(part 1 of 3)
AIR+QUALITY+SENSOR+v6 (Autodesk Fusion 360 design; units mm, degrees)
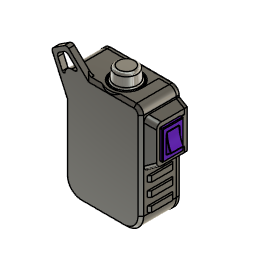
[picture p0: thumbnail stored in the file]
part number: flat_cable
part number: smd_capacitor (7)
part number: SOT-23_XC6206 v3
part number: 472_smd_resistor (1)
part number: smd_capacitor (6)
part number: smd_capacitor (5)
part number: smd_capacitor (4)
part number: smd_capacitor (3)
part number: board
part number: screen
part number: pin_header
part number: soldering
part number: smd_capacitor
part number: smd_capacitor (1)
part number: 914_smd_resistor
part number: 472_smd_resistor
part number: t4_smd_diode
part number: smd_capacitor (2)
sketch "Sketch1" plane through (0, 0, 0) normal (0, 0, 1) x axis (1, 0, 0)
  line L1 (13.5, 15.5) -> (-18.5, 15.5)
  line L2 (13.5, -4.5) -> (13.5, 15.5)
  line L3 (-18.5, -4.5) -> (13.5, -4.5)
  line L4 (-18.5, 15.5) -> (-18.5, -4.5)
  line L5 (13.5, 5.5) -> (-18.5, 5.5)
  line L6 (-2.5, -4.5) -> (-2.5, 15.5)
  line L7 (11, 13) -> (-16, 13)
  line L8 (11, -2) -> (11, 13)
  line L9 (-16, -2) -> (11, -2)
  line L10 (-16, 13) -> (-16, -2)
  line L11 (11.5, -9) -> (11.5, 19)
  circle C1 centre (-16, 13) radius 1.5
  circle C2 centre (-16, -2) radius 1.5
  circle C3 centre (11, 13) radius 1.5
  circle C4 centre (11, -2) radius 1.5
  circle C5 centre (1.5, 5.5) radius 10
  point P6 (-18.5, 5.5)
  point P7 (13.5, 5.5)
  point P8 (-2.5, 15.5)
  point P9 (-2.5, -4.5)
  point P10 (-16, 13)
  point P14 (-16, 13)
  point P13 (-16, -2)
  point P15 (-16, -2)
  point P11 (11, 13)
  point P16 (11, 13)
  point P12 (11, -2)
  point P17 (11, -2)
  point P2 (-18.5, 15.5)
  point P5 (-18.5, -4.5)
  point P3 (13.5, 15.5)
  horizontal L1
  vertical L2
  horizontal L3
  vertical L4
  midpoint L4 P6
  midpoint L2 P7
  midpoint L1 P8
  midpoint L3 P9
  horizontal L7
  vertical L8
  horizontal L9
  vertical L10
  symmetric L5 L7 L9
  symmetric L6 L8 L10
  coincident P10 P14
  coincident P13 P15
  coincident P11 P16
  coincident P12 P17
  perpendicular L3 L11
  dimension "d1" distance P2 P5 = 20
  dimension "d2" distance P2 P3 = 32
  dimension "d3" distance P10 P11 = 27
  dimension "d4" distance P10 P13 = 15
  dimension "d5" diameter C1 = 3
  dimension "d6" diameter C2 = 3
  dimension "d7" diameter C3 = 3
  dimension "d8" diameter C4 = 3
  dimension "d9" distance L2 L11 = 2
  dimension "d10" diameter C5 = 20
extrude "Extrude1" new body sketch "Sketch1" profile of L1 L2 L3 L4 C1 C2 C3 C4 C5 against normal blind 1.1
extrude "Extrude2" new body sketch "Sketch1" profile of C5 along normal blind 5
sketch "Sketch2" plane through (0, 0, 5) normal (0, 0, 1) x axis (-1, 0, 0)
  circle C1 centre (-1.5, -5.5) radius 10
  circle C2 centre (-1.5, -5.5) radius 8.25
  concentric C1 C2
  dimension "d15" diameter C2 = 16.5
extrude "Extrude3" add sketch "Sketch2" profile of C2 along normal blind 9 taper -5
fillet "Fillet1" radius 2
fillet "Fillet2" radius 1
fillet "Fillet3" radius 0.5
sketch "Sketch3" plane through (0, 0, -1.1) normal (0, 0, -1) x axis (1, 0, 0)
  line L1 (-18.5, 4.5) -> (13.5, 4.5)
  line L2 (-18.5, -15.5) -> (-18.5, 4.5)
  line L3 (13.5, -15.5) -> (-18.5, -15.5)
  line L4 (13.5, 4.5) -> (13.5, -15.5)
  line L5 (-12, 7) -> (-12, -20)
  line L6 (-18.5, -15.5) -> (-18.5, 4.5)
  line L7 (-5, -15) -> (-12, -15)
  line L8 (-5, -8) -> (-5, -15)
  line L9 (-12, -8) -> (-5, -8)
  line L10 (-12, -15) -> (-12, -8)
  line L11 (1.5, 10) -> (1.5, -19)
  line L12 (13.5, 4.5) -> (13.5, -15.5)
  line L13 (8.5, -10.5) -> (11, -10.5)
  line L14 (8.5, -0.5) -> (8.5, -10.5)
  line L15 (11, -0.5) -> (8.5, -0.5)
  line L16 (11, -10.5) -> (11, -0.5)
  line L17 (11, 2) -> (11, -13)
  line L18 (13.5, -5.5) -> (-18.5, -5.5)
  circle C1 centre (11, 2) radius 1.5
  circle C2 centre (11, -13) radius 1.5
  circle C3 centre (-16, 2) radius 1.5
  circle C4 centre (-16, -13) radius 1.5
  circle C5 centre (1.5, -5.5) radius 5
  circle C6 centre (1.5, -10.5) radius 0.5
  circle C7 centre (5.0355, -9.0355) radius 0.5
  circle C8 centre (5.0355, -1.9645) radius 0.5
  circle C9 centre (1.5, -0.5) radius 0.5
  circle C10 centre (-2.0355, -1.9645) radius 0.5
  circle C11 centre (-2.0355, -9.0355) radius 0.5
  point P14 (-12, -15)
  point P22 (1.5, -5.5)
  point P23 (1.5, -5.5)
  point P24 (1.5, -10.5)
  point P30 (11, -10.5)
  point P17 (-12, -8)
  point P15 (-5, -15)
  point P33 (11, -0.5)
  point P31 (8.5, -10.5)
  perpendicular L1 L5
  horizontal L7
  vertical L8
  horizontal L9
  vertical L10
  coincident L5 P14
  perpendicular L1 L11
  coincident P22 P23
  coincident L11 P24
  coincident C5 P24
  horizontal L13
  vertical L14
  horizontal L15
  vertical L16
  coincident P30 L17
  symmetric L13 L15 L18
  dimension "d21" distance L5 L6 = 6.5
  dimension "d22" distance P14 P17 = 7
  dimension "d23" distance P14 P15 = 7
  dimension "d24" distance L11 L12 = 12
  dimension "d25" diameter C5 = 10
  dimension "d26" diameter C6 = 1
  dimension "d29" distance P30 P33 = 10
  dimension "d30" distance P30 P31 = 2.5
  dimension "d28" C-Pattern1-Angle = 360
extrude "Extrude4" new body sketch "Sketch3" profile of L7 L8 L9 L10 along normal blind 5
extrude "Extrude5" new body sketch "Sketch3" profile of C5 C6 C7 C8 C9 C10 C11 along normal blind 5
combine "Combine1"
extrude "Extrude6" new body sketch "Sketch3" profile of L13 L14 L15 L16 L17 L18 along normal blind 2.5
sketch "Sketch6" plane through (0, 0, -6.1) normal (0, 0, -1) x axis (1, 0, 0)
  line L1 (-12, -15) -> (-12, -8)
  line L2 (-5, -15) -> (-12, -15)
  line L3 (-5, -8) -> (-5, -15)
  line L4 (-12, -8) -> (-5, -8)
  circle C1 centre (-8.5, -11.5) radius 1.5
  dimension "d49" diameter C1 = 3
extrude "Extrude9" cut sketch "Sketch6" profile of C1 against normal blind 2
extrude "Extrude10" new body sketch "Sketch6" profile of C1 against normal blind 2
sketch "Sketch7" plane through (0, 0, -6.1) normal (0, 0, -1) x axis (1, 0, 0)
  line L1 (-8.5, -13.4) -> (-8.5, -9.7842)
  line L2 (-6.8, -11.5) -> (-10.3039, -11.5)
  line L3 (-8.2, -9.8) -> (-8.8, -9.8)
  line L4 (-8.2, -13.2) -> (-8.2, -9.8)
  line L5 (-8.8, -13.2) -> (-8.2, -13.2)
  line L6 (-8.8, -9.8) -> (-8.8, -13.2)
  line L7 (-6.8, -11.2) -> (-10.3, -11.2)
  line L8 (-6.8, -11.8) -> (-6.8, -11.2)
  line L9 (-10.3, -11.8) -> (-6.8, -11.8)
  line L10 (-10.3, -11.2) -> (-10.3, -11.8)
  line L11 (-10.0318, -10.8) -> (-9.2, -10.8)
  line L12 (-10.0318, -9.9522) -> (-10.0318, -10.8)
  line L13 (-9.2, -9.9522) -> (-10.0318, -9.9522)
  line L14 (-9.2, -10.8) -> (-9.2, -9.9522)
  line L15 (-10.1, -12.2) -> (-9.2, -12.2)
  line L16 (-10.1, -13.1) -> (-10.1, -12.2)
  line L17 (-9.2, -13.1) -> (-10.1, -13.1)
  line L18 (-9.2, -12.2) -> (-9.2, -13.1)
  circle C1 centre (-8.5, -11.5) radius 1.5
  vertical L1
  perpendicular L1 L2
  horizontal L3
  vertical L4
  horizontal L5
  vertical L6
  horizontal L7
  vertical L8
  horizontal L9
  vertical L10
  horizontal L11
  vertical L12
  horizontal L13
  vertical L14
  horizontal L15
  vertical L16
  horizontal L17
  vertical L18
extrude "Extrude11" cut sketch "Sketch7" profile of C1 L4 L6 L7 L9 L11 L14 L15 L18 against normal blind 0.5
sketch "Sketch8" plane through (0, 0, -3.6) normal (0, 0, -1) x axis (1, 0, 0)
  line L1 (11, -0.5) -> (11, -10.5)
  line L2 (8.5, -0.5) -> (11, -0.5)
  line L3 (8.5, -10.5) -> (8.5, -0.5)
  line L4 (11, -10.5) -> (8.5, -10.5)
  line L5 (11, -5.5) -> (8.5, -5.5)
  line L6 (11, -0.5) -> (8.5, -0.5)
  line L7 (11, -5.5) -> (11, -0.5)
  line L8 (8.5, -5.5) -> (11, -5.5)
  line L9 (8.5, -0.5) -> (8.5, -5.5)
  line L10 (11, -3) -> (8.5, -3)
  line L11 (11, -5.5) -> (8.5, -5.5)
  line L12 (11, -10.5) -> (11, -5.5)
  line L13 (8.5, -10.5) -> (11, -10.5)
  line L14 (8.5, -5.5) -> (8.5, -10.5)
  line L15 (8.5, -8) -> (11, -8)
  line L16 (11, -0.5) -> (8.5, -0.5)
  line L17 (11, -3) -> (11, -0.5)
  line L18 (8.5, -3) -> (11, -3)
  line L19 (8.5, -0.5) -> (8.5, -3)
  line L20 (11, -3) -> (8.5, -3)
  line L21 (11, -5.5) -> (11, -3)
  line L22 (8.5, -5.5) -> (11, -5.5)
  line L23 (8.5, -3) -> (8.5, -5.5)
  line L24 (11, -5.5) -> (8.5, -5.5)
  line L25 (11, -8) -> (11, -5.5)
  line L26 (8.5, -8) -> (11, -8)
  line L27 (8.5, -5.5) -> (8.5, -8)
  line L28 (11, -8) -> (8.5, -8)
  line L29 (11, -10.5) -> (11, -8)
  line L30 (8.5, -10.5) -> (11, -10.5)
  line L31 (8.5, -8) -> (8.5, -10.5)
  line L32 (9.3, -2.1986) -> (10.2, -2.1986)
  line L33 (9.3, -1.2986) -> (9.3, -2.1986)
  line L34 (10.2, -1.2986) -> (9.3, -1.2986)
  line L35 (10.2, -2.1986) -> (10.2, -1.2986)
  line L36 (9.3, -1.2986) -> (10.2, -2.1986)
  line L37 (10.2, -1.2986) -> (9.3, -2.1986)
  line L38 (11, -4.25) -> (8.5, -4.25)
  line L39 (11, -6.75) -> (8.5, -6.75)
  line L40 (11, -9.25) -> (8.5, -9.25)
  line L41 (9.3, -4.7) -> (10.2, -4.7)
  line L42 (9.3, -3.8) -> (9.3, -4.7)
  line L43 (10.2, -3.8) -> (9.3, -3.8)
  line L44 (10.2, -4.7) -> (10.2, -3.8)
  line L45 (9.3, -3.8) -> (10.2, -4.7)
  line L46 (10.2, -3.8) -> (9.3, -4.7)
  line L47 (9.3, -7.2) -> (10.2, -7.2)
  line L48 (9.3, -6.3) -> (9.3, -7.2)
  line L49 (10.2, -6.3) -> (9.3, -6.3)
  line L50 (10.2, -7.2) -> (10.2, -6.3)
  line L51 (9.3, -6.3) -> (10.2, -7.2)
  line L52 (10.2, -6.3) -> (9.3, -7.2)
  line L53 (9.3, -9.7) -> (10.2, -9.7)
  line L54 (9.3, -8.8) -> (9.3, -9.7)
  line L55 (10.2, -8.8) -> (9.3, -8.8)
  line L56 (10.2, -9.7) -> (10.2, -8.8)
  line L57 (9.3, -8.8) -> (10.2, -9.7)
  line L58 (10.2, -8.8) -> (9.3, -9.7)
  point P6 (8.5, -5.5)
  point P7 (11, -5.5)
  point P4 (8.5, -0.5)
  point P8 (8.5, -0.5)
  point P11 (8.5, -3)
  point P12 (11, -3)
  point P2 (11, -10.5)
  point P14 (11, -10.5)
  point P16 (11, -8)
  point P17 (8.5, -8)
  point P25 (11, -10.5)
  point P31 (9.75, -1.7486)
  point P32 (8.5, -4.25)
  point P33 (11, -4.25)
  point P34 (8.5, -6.75)
  point P35 (11, -6.75)
  point P36 (8.5, -9.25)
  point P37 (11, -9.25)
  point P42 (9.75, -4.25)
  point P47 (9.75, -6.75)
  point P52 (9.75, -9.25)
  point P28 (9.3, -2.1986)
  point P29 (9.3, -1.2986)
  point P30 (10.2, -1.2986)
  point P39 (9.3, -4.7)
  point P40 (9.3, -3.8)
  point P41 (10.2, -3.8)
  point P44 (9.3, -7.2)
  point P45 (9.3, -6.3)
  point P46 (10.2, -6.3)
  point P49 (9.3, -9.7)
  point P50 (9.3, -8.8)
  point P51 (10.2, -8.8)
  midpoint L3 P6
  midpoint L1 P7
  horizontal L6
  vertical L7
  horizontal L8
  vertical L9
  coincident P4 P8
  midpoint L9 P11
  midpoint L7 P12
  horizontal L11
  vertical L12
  horizontal L13
  vertical L14
  coincident P2 P14
  midpoint L12 P16
  midpoint L14 P17
  horizontal L16
  vertical L17
  horizontal L18
  vertical L19
  horizontal L20
  vertical L21
  horizontal L22
  vertical L23
  horizontal L24
  vertical L25
  horizontal L26
  vertical L27
  horizontal L28
  vertical L29
  horizontal L30
  vertical L31
  coincident P2 P25
  perpendicular L32 L33
  parallel L32 L34
  parallel L33 L35
  horizontal L32
  coincident L36 P31
  coincident L37 P31
  midpoint L23 P32
  midpoint L21 P33
  midpoint L27 P34
  midpoint L25 P35
  midpoint L31 P36
  midpoint L29 P37
  perpendicular L41 L42
  parallel L41 L43
  parallel L42 L44
  horizontal L41
  coincident L45 P42
  coincident L46 P42
  midpoint L38 P42
  perpendicular L47 L48
  parallel L47 L49
  parallel L48 L50
  horizontal L47
  coincident L51 P47
  coincident L52 P47
  midpoint L39 P47
  perpendicular L53 L54
  parallel L53 L55
  parallel L54 L56
  horizontal L53
  coincident L57 P52
  coincident L58 P52
  midpoint L40 P52
  dimension "d56" distance P28 P29 = 0.9
  dimension "d57" distance P29 P30 = 0.9
  dimension "d58" distance P39 P40 = 0.9
  dimension "d59" distance P40 P41 = 0.9
  dimension "d60" distance P44 P45 = 0.9
  dimension "d61" distance P45 P46 = 0.9
  dimension "d62" distance P49 P50 = 0.9
  dimension "d63" distance P50 P51 = 0.9
extrude "Extrude12" new body sketch "Sketch8" profile of L32 L33 L34 L35 L38 L39 L40 L41 L42 L43 L44 L47 L48 L49 L50 L53 L54 L55 L56 along normal blind 2
sketch "Sketch9" plane through (10.2, 0, 0) normal (1, 0, 0) x axis (0, 1, 0)
  line L1 (8.8, -3.6) -> (9.7, -3.6)
  line L2 (8.8, -5.6) -> (8.8, -3.6)
  line L3 (9.7, -5.6) -> (8.8, -5.6)
  line L4 (9.7, -3.6) -> (9.7, -5.6)
  line L5 (2.1986, -5.6) -> (1.2986, -5.6)
  line L6 (2.1986, -4.7) -> (2.1986, -5.6)
  line L7 (1.2986, -4.7) -> (2.1986, -4.7)
  line L8 (1.2986, -5.6) -> (1.2986, -4.7)
  line L9 (4.7, -5.6) -> (3.8, -5.6)
  line L10 (4.7, -4.7) -> (4.7, -5.6)
  line L11 (3.8, -4.7) -> (4.7, -4.7)
  line L12 (3.8, -5.6) -> (3.8, -4.7)
  line L13 (4.7, -5.6) -> (4.7, -3.6)
  line L14 (7.2, -4.7) -> (6.3, -4.7)
  line L15 (7.2, -5.6) -> (7.2, -4.7)
  line L16 (6.3, -5.6) -> (7.2, -5.6)
  line L17 (6.3, -4.7) -> (6.3, -5.6)
  line L18 (6.3, -5.6) -> (6.3, -3.6)
  line L19 (9.7, -4.7) -> (8.8, -4.7)
  line L20 (9.7, -5.6) -> (9.7, -4.7)
  line L21 (8.8, -5.6) -> (9.7, -5.6)
  line L22 (8.8, -4.7) -> (8.8, -5.6)
  point P6 (1.2986, -5.6)
  point P10 (1.2986, -5.6)
  point P13 (4.7, -4.7)
  point P11 (3.8, -5.6)
  point P15 (3.8, -5.6)
  point P20 (7.2, -5.6)
  point P24 (7.2, -5.6)
  point P18 (6.3, -4.7)
  point P5 (9.7, -5.6)
  point P27 (9.7, -5.6)
  point P25 (8.8, -4.7)
  point P7 (2.1986, -5.6)
  point P9 (1.2986, -4.7)
  horizontal L5
  vertical L6
  horizontal L7
  vertical L8
  coincident P6 P10
  horizontal L9
  vertical L10
  horizontal L11
  vertical L12
  coincident P13 L13
  coincident P11 P15
  horizontal L14
  vertical L15
  horizontal L16
  vertical L17
  coincident P20 P24
  coincident P18 L18
  horizontal L19
  vertical L20
  horizontal L21
  vertical L22
  coincident P5 P27
  coincident L2 P25
  dimension "d66" distance P6 P7 = 0.9
  dimension "d67" distance P6 P9 = 0.9
extrude "Extrude13" add sketch "Sketch9" profile of L2 L3 L4 L5 L6 L7 L8 L9 L10 L11 L12 L13 L14 L15 L16 L17 L18 L19 L20 L21 L22 along normal blind 8
fillet "Fillet4" radius 0.8
chamfer "Chamfer1" distance 0.3
copy_paste_bodies "CutPasteBodies"
sketch "Sketch10" plane through (0, 0, 0) normal (0, 1, 0) x axis (1, 0, 0)
  line L1 (-13, 37.5) -> (13, 37.5)
  line L2 (-25, -32.5) -> (-25, 25.5)
  line L3 (20, -37.5) -> (-20, -37.5)
  line L4 (25, 25.5) -> (25, -32.5)
  line L5 (-25, -37.5) -> (25, 37.5)
  line L6 (25, -37.5) -> (-25, 37.5)
  arc A1 centre (13, 25.5) radius 12 clockwise from (13, 37.5) to (25, 25.5)
  arc A2 centre (-13, 25.5) radius 12 clockwise from (-25, 25.5) to (-13, 37.5)
  arc A3 centre (20, -32.5) radius 5 clockwise from (25, -32.5) to (20, -37.5)
  arc A4 centre (-20, -32.5) radius 5 clockwise from (-20, -37.5) to (-25, -32.5)
  point P6 (0, 0)
  point P1 (0, 0)
  point P2 (25, 37.5)
  point P3 (-25, 37.5)
  point P5 (25, -37.5)
  point P4 (-25, -37.5)
  horizontal L1
  perpendicular L1 L2
  parallel L1 L3
  parallel L2 L4
  coincident L5 P6
  coincident L6 P6
  coincident P1 P6
  coincident P2 L4
  coincident P2 L1
  tangent L4 A1
  tangent L1 A1
  coincident P3 L2
  coincident P3 L1
  tangent L2 A2
  tangent L1 A2
  equal A1 A2
  coincident P5 L4
  coincident P5 L3
  tangent L4 A3
  tangent L3 A3
  coincident P4 L3
  coincident P4 L2
  tangent L3 A4
  tangent L2 A4
  equal A3 A4
  dimension "d41" distance P4 P5 = 50
  dimension "d42" distance P3 P4 = 75
  dimension "d43" radius A1 = 12
  dimension "d44" radius A3 = 5
extrude "Extrude14" new body sketch "Sketch10" profile of L1 L2 L3 L4 A1 A2 A3 A4 along normal blind 25
work_plane "WorkPlane1" AlongDistance -2
split "Split1"
base_feature "Base Feature1"
base_feature "Base Feature1"
base_feature "Base Feature1"
base_feature "Base Feature1"
base_feature "Base Feature1"
base_feature "Base Feature1"
base_feature "Base Feature1"
base_feature "Base Feature1"
base_feature "Base Feature1"
base_feature "Base Feature1"
base_feature "Base Feature1"
base_feature "Base Feature1"
base_feature "Base Feature1"
base_feature "Base Feature1"
base_feature "Base Feature1"
base_feature "Base Feature1"
base_feature "Base Feature1"
base_feature "Base Feature1"
base_feature "Base Feature1"
position "Position1"
sketch "Sketch11" plane through (0, 32, 0) normal (0, 1, 0) x axis (-1, 0, 0)
  line L1 (-20, 32.65) -> (20, 32.65)
  line L2 (-20, 0.65) -> (-20, 32.65)
  line L3 (20, 0.65) -> (-20, 0.65)
  line L4 (20, 32.65) -> (20, 0.65)
  line L5 (-20, 0.65) -> (20, 32.65)
  line L6 (20, 0.65) -> (-20, 32.65)
  point P4 (-20, 0.65)
  point P5 (20, 0.65)
  point P3 (-20, 32.65)
  horizontal L1
  perpendicular L1 L2
  parallel L1 L3
  parallel L2 L4
  dimension "d48" distance P4 P5 = 40
  dimension "d72" distance P3 P4 = 32
extrude "Extrude15" new body sketch "Sketch11" profile of L1 L2 L3 L4 against normal blind 7
fillet "Fillet5" radius 6.5
draft "Draft1" Angle1 25 Angle2 0
sketch "Sketch12" plane through (0, 25, 0) normal (0, 1, 0) x axis (-1, 0, 0)
  line L1 (-20, 37.5) -> (20, 37.5)
  line L2 (-25, -25.5) -> (-25, 32.5)
  line L3 (13, -37.5) -> (-13, -37.5)
  line L4 (25, 32.5) -> (25, -25.5)
  line L5 (-13, -25.5) -> (-25, -25.5)
  line L6 (-13, -37.5) -> (-13, -25.5)
  line L7 (-25, -37.5) -> (-13, -37.5)
  line L8 (-25, -25.5) -> (-25, -37.5)
  line L9 (-8, -37.5) -> (-25, -37.5)
  line L10 (-8, -20.5) -> (-8, -37.5)
  line L11 (-25, -20.5) -> (-8, -20.5)
  line L12 (-25, -37.5) -> (-25, -20.5)
  arc A1 centre (20, 32.5) radius 5 clockwise from (20, 37.5) to (25, 32.5)
  arc A2 centre (-20, 32.5) radius 5 clockwise from (-25, 32.5) to (-20, 37.5)
  arc A3 centre (-13, -25.5) radius 12 clockwise from (-13, -37.5) to (-25, -25.5)
  arc A4 centre (13, -25.5) radius 12 clockwise from (25, -25.5) to (13, -37.5)
  circle C1 centre (-8, -20.5) radius 12.5
  point P9 (-13, -37.5)
  point P16 (-13, -37.5)
  point P8 (-25, -25.5)
  point P14 (-25, -25.5)
  point P19 (-8, -20.5)
  point P21 (-8, -20.5)
  point P17 (-25, -37.5)
  point P18 (-8, -37.5)
  point P20 (-25, -20.5)
  horizontal L5
  vertical L6
  horizontal L7
  vertical L8
  coincident P9 P16
  coincident P8 P14
  horizontal L9
  vertical L10
  horizontal L11
  vertical L12
  coincident P19 P21
  dimension "d79" distance P17 P18 = 17
  dimension "d80" distance P17 P20 = 17
  dimension "d81" diameter C1 = 25
extrude "Extrude16" new body sketch "Sketch12" profile of L5 L6 L10 L11 C1 along normal blind 7
draft "Draft2" Angle1 15 Angle2 0
position "Position2"
split "Split1"
remove_body "RemoveBody1"
remove_body "RemoveBody2"
remove_body "RemoveBody3"
remove_body "RemoveBody4"
position "Position3"
chamfer "Chamfer2" distance 2
sketch "Sketch13" plane through (0, 0, 0) normal (0, -1, 0) x axis (1, 0, 0)
  line L1 (-23, -25.5) -> (-23, 32.5)
  line L2 (13, -35.5) -> (-13, -35.5)
  line L3 (23, 32.5) -> (23, -25.5)
  line L4 (-20, 35.5) -> (20, 35.5)
  arc A1 centre (-13, -25.5) radius 10 clockwise from (-13, -35.5) to (-23, -25.5)
  arc A2 centre (13, -25.5) radius 10 clockwise from (23, -25.5) to (13, -35.5)
  arc A3 centre (20, 32.5) radius 3 clockwise from (20, 35.5) to (23, 32.5)
  arc A4 centre (-20, 32.5) radius 3 clockwise from (-23, 32.5) to (-20, 35.5)
  circle C1 centre (-20, 32.5) radius 12.5
  circle C2 centre (-20, 32.5) radius 8.5
  concentric A4 C1
  concentric A4 C2
  dimension "d87" diameter C1 = 25
  dimension "d88" diameter C2 = 17
extrude "Extrude17" new body sketch "Sketch13" profile of L1 L4 C1 C2 against normal blind 7
shell "Shell1" innerThickness 1.3
position "Position4"
sketch "Sketch14" plane through (0, 0, 37.5) normal (0, 0, 1) x axis (-1, 0, 0)
  line L1 (-20, -2) -> (20, -2)
  line L2 (-20, -23) -> (-20, -2)
  line L3 (20, -23) -> (-20, -23)
  line L4 (20, -2) -> (20, -23)
  line L5 (-20, -2) -> (-20, 0)
  line L6 (20, -2) -> (-20, -2)
  line L7 (20, 0) -> (20, -2)
  line L8 (-20, 0) -> (20, 0)
  circle C1 centre (-4, -11.5) radius 10
  circle C2 centre (-4, -11.5) radius 10.5
  circle C3 centre (-4, -11.5) radius 11.5
  concentric C1 C3
  tangent L8 C3
  dimension "d92" = 0.5
extrude "Extrude18" new body sketch "Sketch14" profile of L1 C2 L6 C3 against normal blind 1.3
move_face "MoveFace1"
move "Move1"
position "Position5"
move_face "MoveFace2"
combine "Combine2"
delete_face "DeleteFace1"
offset_faces "OffsetFaces1" distance 1
offset_faces "OffsetFaces2" distance -1
combine "Combine3"
delete_face "DeleteFace2"
delete_face "DeleteFace3"
chamfer "Chamfer3" distance 1
move "Move2"
shell "Shell2" innerThickness 1.2
shell "Shell3" innerThickness 1.2
combine "Combine4"
extrude "Extrude19" cut of existing geometry blind -15
extrude "Extrude20" cut of existing geometry blind -2
sketch "Sketch15" plane through (0, 34, 0) normal (0, 1, 0) x axis (-1, 0, 0)
  line L1 (-20, 7.15) -> (-20, 26.15)
  line L2 (13.5, 0.65) -> (-13.5, 0.65)
  line L3 (20, 26.15) -> (20, 7.15)
  line L4 (-13.5, 32.65) -> (13.5, 32.65)
  arc A1 centre (-13.5, 26.15) radius 6.5 clockwise from (-20, 26.15) to (-13.5, 32.65)
  arc A2 centre (-13.5, 7.15) radius 6.5 clockwise from (-13.5, 0.65) to (-20, 7.15)
  arc A3 centre (13.5, 7.15) radius 6.5 clockwise from (20, 7.15) to (13.5, 0.65)
  arc A4 centre (13.5, 26.15) radius 6.5 clockwise from (13.5, 32.65) to (20, 26.15)
position "Position6"
sketch "Sketch16" plane through (0, 34, 0) normal (0, 1, 0) x axis (-1, 0, 0)
  line L1 (12.35, 9.4) -> (-12.35, 9.4)
  line L2 (12.35, 23.9) -> (12.35, 9.4)
  line L3 (-12.35, 23.9) -> (12.35, 23.9)
  line L4 (-12.35, 9.4) -> (-12.35, 23.9)
  line L5 (12.35, 9.4) -> (-12.35, 23.9)
  line L6 (-13, 24.65) -> (13, 24.65)
  line L7 (-13, 8.65) -> (-13, 24.65)
  line L8 (13, 8.65) -> (-13, 8.65)
  line L9 (13, 24.65) -> (13, 8.65)
  line L10 (-13, 8.65) -> (13, 24.65)
  line L11 (13, 8.65) -> (-13, 24.65)
  point P5 (-12.35, 23.9)
  point P6 (-12.35, 23.9)
  point P3 (12.35, 9.4)
  point P7 (12.35, 9.4)
  point P12 (0, 16.65)
  point P10 (-13, 8.65)
  point P11 (13, 8.65)
  point P9 (-13, 24.65)
  coincident P5 P6
  coincident P3 P7
  horizontal L6
  perpendicular L6 L7
  parallel L6 L8
  parallel L7 L9
  coincident L10 P12
  coincident L11 P12
  midpoint L5 P12
  dimension "d104" distance P10 P11 = 26
  dimension "d105" distance P9 P10 = 16
extrude "Extrude21" cut sketch "Sketch16" profile of L1 L2 L3 L4 L5 L6 L7 L8 L9 against normal blind 1.2
fillet "Fillet6" radius 1
position "Position7"
sketch "Sketch17" plane through (0, 32.8, 0) normal (0, -1, 0) x axis (1, 0, 0)
  line L1 (12, 24.65) -> (-12, 24.65)
  line L2 (13, 9.65) -> (13, 23.65)
  line L3 (-12, 8.65) -> (12, 8.65)
  line L4 (-13, 23.65) -> (-13, 9.65)
  line L5 (-13.5, 31.8855) -> (13.5, 31.8855)
  line L6 (-19.2355, 7.15) -> (-19.2355, 26.15)
  line L7 (13.5, 1.4145) -> (-13.5, 1.4145)
  line L8 (19.2355, 26.15) -> (19.2355, 7.15)
  line L9 (-7.0654, 4.3439) -> (-7.0652, 4.3437)
  line L10 (-7.0651, 4.3439) -> (-7.0654, 4.3439)
  line L11 (-7.0651, 4.3439) -> (7.0651, 4.3439)
  line L12 (7.0654, 4.3439) -> (7.0651, 4.3439)
  line L13 (7.0652, 4.3437) -> (7.0654, 4.3439)
  curve K1 (7.0652, 4.3437) -> (6.7021, 4.0382)
  line L14 (6.7019, 4.038) -> (-6.7019, 4.038)
  curve K2 (-6.7022, 4.0382) -> (-7.0652, 4.3437)
  line L15 (12.7, 2.2) -> (-12.7, 2.2)
  line L16 (12.7, 28.4) -> (12.7, 2.2)
  line L17 (-12.7, 28.4) -> (12.7, 28.4)
  line L18 (-12.7, 2.2) -> (-12.7, 28.4)
  line L19 (-11, 11.2) -> (-11, 8.2)
  line L20 (11, 11.2) -> (-11, 11.2)
  line L21 (11, 8.2) -> (11, 11.2)
  line L22 (-11, 8.2) -> (11, 8.2)
  line L23 (0, 2.2) -> (0, 28.4)
  line L24 (-27.6247, 16.3) -> (27.6247, 16.3)
  line L25 (-27.6247, 14.3) -> (-27.6247, 16.3)
  line L26 (27.6247, 14.3) -> (-27.6247, 14.3)
  line L27 (27.6247, 16.3) -> (27.6247, 14.3)
  line L28 (-27.6247, 14.3) -> (27.6247, 16.3)
  line L29 (27.6247, 14.3) -> (-27.6247, 16.3)
  line L30 (-1, 42.0544) -> (1, 42.0544)
  line L31 (-1, -11.4544) -> (-1, 42.0544)
  line L32 (1, -11.4544) -> (-1, -11.4544)
  line L33 (1, 42.0544) -> (1, -11.4544)
  line L34 (-1, -11.4544) -> (1, 42.0544)
  line L35 (1, -11.4544) -> (-1, 42.0544)
  line L36 (13.2, 1.7) -> (-13.2, 1.7)
  line L37 (13.2, 28.9) -> (13.2, 1.7)
  line L38 (-13.2, 28.9) -> (13.2, 28.9)
  line L39 (-13.2, 1.7) -> (-13.2, 28.9)
  arc A1 centre (12, 23.65) radius 1 clockwise from (12, 24.65) to (13, 23.65)
  arc A2 centre (12, 9.65) radius 1 clockwise from (13, 9.65) to (12, 8.65)
  arc A3 centre (-12, 9.65) radius 1 clockwise from (-12, 8.65) to (-13, 9.65)
  arc A4 centre (-12, 23.65) radius 1 clockwise from (-13, 23.65) to (-12, 24.65)
  arc A5 centre (13.5, 26.15) radius 5.7355 clockwise from (13.5, 31.8855) to (19.2355, 26.15)
  arc A6 centre (-13.5, 26.15) radius 5.7355 clockwise from (-19.2355, 26.15) to (-13.5, 31.8855)
  arc A7 centre (-13.5, 7.15) radius 5.7355 clockwise from (-13.5, 1.4145) to (-19.2355, 7.15)
  arc A8 centre (13.5, 7.15) radius 5.7355 clockwise from (19.2355, 7.15) to (13.5, 1.4145)
  circle C1 centre (-3.81, 27.13) radius 0.6
  circle C2 centre (-1.27, 27.13) radius 0.6
  circle C3 centre (1.27, 27.13) radius 0.6
  circle C4 centre (3.81, 27.13) radius 0.6
  circle C5 centre (10.7, 26.4) radius 1.5
  circle C6 centre (-10.7, 26.4) radius 1.5
  circle C7 centre (10.7, 4.2) radius 1.5
  circle C8 centre (-10.7, 4.2) radius 1.5
  point P52 (0, 28.4)
  point P53 (0, 2.2)
  point P58 (0, 15.3)
  point P63 (0, 15.3)
  point P55 (-27.6247, 16.3)
  point P56 (-27.6247, 14.3)
  point P61 (-1, -11.4544)
  point P62 (1, -11.4544)
  midpoint L17 P52
  midpoint L15 P53
  horizontal L24
  perpendicular L24 L25
  parallel L24 L26
  parallel L25 L27
  coincident L28 P58
  coincident L29 P58
  midpoint L23 P58
  horizontal L30
  perpendicular L30 L31
  parallel L30 L32
  parallel L31 L33
  coincident L34 P63
  coincident L35 P63
  coincident P58 P63
  dimension "d110" distance P55 P56 = 2
  dimension "d111" distance P61 P62 = 2
  dimension "d112" = 0.5
extrude "Extrude22" new body sketch "Sketch17" profile of L5 L6 L7 L8 L24 L26 L31 L33 L36 L38 L37 L39 along normal blind 6.1
move_face "MoveFace3"
rectangular_pattern "R-Pattern1" uSpaceDistance 11 vSpaceDistance 0
rectangular_pattern "R-Pattern2" uSpaceDistance 11 vSpaceDistance 0
base_feature "Base Feature1"
base_feature "Base Feature1"
base_feature "Base Feature1"
position "Position2"
remove_instance "RemoveInstance1"
remove_instance "RemoveInstance2"
delete_face "DeleteFace1"
split "Split1"
mirror "Mirror1" mirrorStitchTolerance 0.1 named "d112_1"
combine "Combine1"
move "Move1"
move "Move2"
position "Position8"
position "Position9"
offset_faces "OffsetFaces3" distance 2
offset_faces "OffsetFaces4" distance -2
move_face "MoveFace4"
position "Position10"
offset_faces "OffsetFaces5" distance 2
offset_faces "OffsetFaces6" distance 2
offset_faces "OffsetFaces7" distance 2
move_face "MoveFace5"
sketch "Sketch18" plane through (0, 0, 41.5) normal (0, 0, 1) x axis (-1, 0, 0)
  line L1 (-13.1652, -4) -> (-10.1644, -4)
  line L2 (2.1644, -4) -> (5.1652, -4)
  arc A1 centre (-4, -12.5) radius 10.5 clockwise from (2.1644, -4) to (-10.1644, -4)
  arc A2 centre (-4, -12.5) radius 12.5 clockwise from (5.1652, -4) to (-13.1652, -4)
  circle C1 centre (-4, -12.5) radius 12.5
  circle C2 centre (-4, -12.5) radius 10.5
  point P6 (5.1652, -4)
  point P3 (2.1644, -4)
  concentric A1 C1
  coincident P6 C1
  concentric A1 C2
  coincident P3 C2
extrude "Extrude23" new body sketch "Sketch18" profile of L1 L2 C1 C2 against normal blind 4
combine "Combine5"
move_face "MoveFace6"
combine "Combine6"
delete_face "DeleteFace4"
delete_face "DeleteFace5"
delete_face "DeleteFace6"
delete_face "DeleteFace7"
delete_face "DeleteFace8"
delete_face "DeleteFace9"
delete_face "DeleteFace10"
delete_face "DeleteFace11"
extrude "Extrude24" cut of existing geometry blind -24
sketch "Sketch19" plane through (0, 31, 0) normal (0, 1, 0) x axis (-1, 0, 0)
  line L1 (-14.975, -30.405) -> (-14.975, -10.595)
  line L2 (-1.025, -30.405) -> (-14.975, -30.405)
  line L3 (-1.025, -10.595) -> (-1.025, -30.405)
  line L4 (-14.975, -10.595) -> (-1.025, -10.595)
  line L5 (-12.2, -27.65) -> (-3.8, -27.65)
  curve K1 (-12.2, -27.65) -> (-12.9, -26.8848)
  line L6 (-12.9, -17.1081) -> (-12.9, -26.8848)
  curve K2 (-12.9, -17.1081) -> (-12.2, -13.35)
  line L7 (-3.8, -13.35) -> (-12.2, -13.35)
  curve K3 (-3.8, -13.35) -> (-3.1, -17.1081)
  line L8 (-3.1, -26.8848) -> (-3.1, -17.1081)
  curve K4 (-3.1, -26.8848) -> (-3.8, -27.65)
  line L9 (0.975, -32.405) -> (-16.975, -32.405)
  line L10 (0.975, -8.595) -> (0.975, -32.405)
  line L11 (-16.975, -8.595) -> (0.975, -8.595)
  line L12 (-16.975, -32.405) -> (-16.975, -8.595)
  line L13 (-1.025, -30.405) -> (-14.975, -10.595)
  line L14 (-14.5, -10.5) -> (-1.5, -10.5)
  line L15 (-14.5, -30.5) -> (-14.5, -10.5)
  line L16 (-1.5, -30.5) -> (-14.5, -30.5)
  line L17 (-1.5, -10.5) -> (-1.5, -30.5)
  line L18 (-14.5, -30.5) -> (-1.5, -10.5)
  line L19 (-1.5, -30.5) -> (-14.5, -10.5)
  circle C1 centre (-8, -20.5) radius 15.3744
  point P3 (-14.975, -10.595)
  point P19 (-14.975, -10.595)
  point P5 (-1.025, -30.405)
  point P20 (-1.025, -30.405)
  point P25 (-8, -20.5)
  point P2 (-8, -20.5)
  point P23 (-14.5, -30.5)
  point P24 (-1.5, -30.5)
  point P22 (-14.5, -10.5)
  coincident P3 P19
  coincident P5 P20
  horizontal L14
  perpendicular L14 L15
  parallel L14 L16
  parallel L15 L17
  coincident L18 P25
  coincident L19 P25
  coincident P2 P25
  dimension "d132" = 2
  dimension "d133" distance P23 P24 = 13
  dimension "d134" distance P22 P23 = 20
extrude "Extrude25" cut sketch "Sketch19" profile of L2 L4 L5 K1 L6 K2 L7 K3 L8 K4 L13 L14 L15 L16 L17 against normal blind 1.2
delete_face "DeleteFace12"
offset_faces "OffsetFaces8" distance -3
offset_faces "OffsetFaces9" distance 1
chamfer "Chamfer4" distance 0.5
sketch "Sketch20" plane through (-27, 0, 0) normal (-1, 0, 0) x axis (0, -1, 0)
  line L1 (-7, 22.7532) -> (-7, 21.5455)
  curve K1 (-6.5, 23.3759) -> (-7, 22.7532)
  line L2 (-1.8, 23.3759) -> (-6.5, 23.3759)
  line L3 (-1.8, 34.5) -> (-1.8, 23.3759)
  line L4 (-25, 34.5) -> (-1.8, 34.5)
  line L5 (-25, -27.5) -> (-25, 34.5)
  line L6 (-1.8, -27.5) -> (-25, -27.5)
  line L7 (-1.8, 20.9566) -> (-1.8, -27.5)
  line L8 (-6.5, 20.9566) -> (-1.8, 20.9566)
  curve K2 (-7, 21.5455) -> (-6.5, 20.9566)
  line L9 (-1.8, 3.5) -> (-25, 3.5)
  line L10 (-22.4, 5.5) -> (-4.4, 5.5)
  line L11 (-22.4, 1.5) -> (-22.4, 5.5)
  line L12 (-4.4, 1.5) -> (-22.4, 1.5)
  line L13 (-4.4, 5.5) -> (-4.4, 1.5)
  line L14 (-22.4, 1.5) -> (-4.4, 5.5)
  line L15 (-4.4, 1.5) -> (-22.4, 5.5)
  point P12 (-25, 3.5)
  point P13 (-1.8, 3.5)
  point P18 (-13.4, 3.5)
  point P16 (-22.4, 1.5)
  point P17 (-4.4, 1.5)
  point P15 (-22.4, 5.5)
  midpoint L5 P12
  coincident L7 P13
  perpendicular L7 L9
  horizontal L10
  perpendicular L10 L11
  parallel L10 L12
  parallel L11 L13
  coincident L14 P18
  coincident L15 P18
  midpoint L9 P18
  dimension "d140" distance P16 P17 = 18
  dimension "d141" distance P15 P16 = 4
extrude "Extrude26" new body sketch "Sketch20" profile of L10 L11 L12 L13 along normal blind 1.5
chamfer "Chamfer5" distance 1.5
rectangular_pattern "R-Pattern3" uSpaceDistance -28 vSpaceDistance 0
mirror "Mirror1" mirrorStitchTolerance 0.1
combine "Combine7"
delete_face "DeleteFace13"
sketch "Sketch21" plane through (0, 25, 0) normal (0, 1, 0) x axis (-1, 0, 0)
  line L1 (-4, 39.5) -> (22, 39.5)
  line L2 (-22, 39.5) -> (-4, 39.5)
  line L3 (-27, -27.5) -> (-27, 34.5)
  line L4 (15, -39.5) -> (-15, -39.5)
  line L5 (27, 34.5) -> (27, -27.5)
  line L6 (-23.7, 32.5) -> (-23.7, -25.5)
  line L7 (20, 36.2) -> (-20, 36.2)
  line L8 (23.7, -25.5) -> (23.7, 32.5)
  line L9 (-13, -36.2) -> (13, -36.2)
  line L10 (-25.8, -27.5) -> (-25.8, 34.5)
  line L11 (15, -38.3) -> (-15, -38.3)
  line L12 (25.8, 34.5) -> (25.8, -27.5)
  line L13 (-4, 38.3) -> (22, 38.3)
  line L14 (-22, 38.3) -> (-4, 38.3)
  arc A1 centre (-22, 34.5) radius 5 clockwise from (-27, 34.5) to (-22, 39.5)
  arc A2 centre (-15, -27.5) radius 12 clockwise from (-15, -39.5) to (-27, -27.5)
  arc A3 centre (15, -27.5) radius 12 clockwise from (27, -27.5) to (15, -39.5)
  arc A4 centre (22, 34.5) radius 5 clockwise from (22, 39.5) to (27, 34.5)
  arc A5 centre (-13, -25.5) radius 10.7 clockwise from (-13, -36.2) to (-23.7, -25.5)
  arc A6 centre (-20, 32.5) radius 3.7 clockwise from (-23.7, 32.5) to (-20, 36.2)
  arc A7 centre (20, 32.5) radius 3.7 clockwise from (20, 36.2) to (23.7, 32.5)
  arc A8 centre (13, -25.5) radius 10.7 clockwise from (23.7, -25.5) to (13, -36.2)
  arc A9 centre (-15, -27.5) radius 10.8 clockwise from (-15, -38.3) to (-25.8, -27.5)
  arc A10 centre (15, -27.5) radius 10.8 clockwise from (25.8, -27.5) to (15, -38.3)
  arc A11 centre (22, 34.5) radius 3.8 clockwise from (22, 38.3) to (25.8, 34.5)
  arc A12 centre (-22, 34.5) radius 3.8 clockwise from (-25.8, 34.5) to (-22, 38.3)
  dimension "d151" = -1.2
extrude "Extrude27" cut sketch "Sketch21" profile of A5 L6 A6 L7 A7 L8 A8 L9 L10 A11 A9 L11 A10 L12 A12 L13 L14 against normal blind 23.7
chamfer "Chamfer6" distance 2
sketch "Sketch22" plane through (0, 27, 0) normal (0, 1, 0) x axis (-1, 0, 0)
  line L1 (-23.2642, 26.15) -> (-23.2642, 7.15)
  line L2 (13.5, 35.9142) -> (-13.5, 35.9142)
  line L3 (23.2642, 7.15) -> (23.2642, 26.15)
  line L4 (-13.5, -2.6142) -> (13.5, -2.6142)
  line L5 (-27, -27.5) -> (-27, 34.5)
  line L6 (15, -39.5) -> (-15, -39.5)
  line L7 (27, 34.5) -> (27, -27.5)
  line L8 (-22, 39.5) -> (22, 39.5)
  line L9 (-25.8, 34.5) -> (-25.8, -27.5)
  line L10 (22, 38.3) -> (-22, 38.3)
  line L11 (25.8, -27.5) -> (25.8, 34.5)
  line L12 (-15, -38.3) -> (15, -38.3)
  line L13 (-4, 39.5) -> (22, 39.5)
  line L14 (-22, 39.5) -> (-4, 39.5)
  line L15 (-27, -27.5) -> (-27, 34.5)
  line L16 (15, -39.5) -> (-15, -39.5)
  line L17 (27, 34.5) -> (27, -27.5)
  line L18 (22, 38.1) -> (-22, 38.1)
  line L19 (-25.6, 34.5) -> (-25.6, -27.5)
  line L20 (-15, -38.1) -> (15, -38.1)
  line L21 (25.6, -27.5) -> (25.6, 34.5)
  line L22 (-24.1, 34.5) -> (-24.1, -27.5)
  line L23 (22, 36.6) -> (-22, 36.6)
  line L24 (24.1, -27.5) -> (24.1, 34.5)
  line L25 (-15, -36.6) -> (15, -36.6)
  arc A1 centre (-13.5, 7.15) radius 9.7642 clockwise from (-13.5, -2.6142) to (-23.2642, 7.15)
  arc A2 centre (-13.5, 26.15) radius 9.7642 clockwise from (-23.2642, 26.15) to (-13.5, 35.9142)
  arc A3 centre (13.5, 26.15) radius 9.7642 clockwise from (13.5, 35.9142) to (23.2642, 26.15)
  arc A4 centre (13.5, 7.15) radius 9.7642 clockwise from (23.2642, 7.15) to (13.5, -2.6142)
  arc A5 centre (-15, -27.5) radius 12 clockwise from (-15, -39.5) to (-27, -27.5)
  arc A6 centre (15, -27.5) radius 12 clockwise from (27, -27.5) to (15, -39.5)
  arc A7 centre (22, 34.5) radius 5 clockwise from (22, 39.5) to (27, 34.5)
  arc A8 centre (-22, 34.5) radius 5 clockwise from (-27, 34.5) to (-22, 39.5)
  circle C1 centre (-8, -20.5) radius 16.4462
  arc A9 centre (-22, 34.5) radius 3.8 clockwise from (-25.8, 34.5) to (-22, 38.3)
  arc A10 centre (22, 34.5) radius 3.8 clockwise from (22, 38.3) to (25.8, 34.5)
  arc A11 centre (15, -27.5) radius 10.8 clockwise from (25.8, -27.5) to (15, -38.3)
  arc A12 centre (-15, -27.5) radius 10.8 clockwise from (-15, -38.3) to (-25.8, -27.5)
  arc A13 centre (-22, 34.5) radius 5 clockwise from (-27, 34.5) to (-22, 39.5)
  arc A14 centre (-15, -27.5) radius 12 clockwise from (-15, -39.5) to (-27, -27.5)
  arc A15 centre (15, -27.5) radius 12 clockwise from (27, -27.5) to (15, -39.5)
  arc A16 centre (22, 34.5) radius 5 clockwise from (22, 39.5) to (27, 34.5)
  arc A17 centre (22, 34.5) radius 3.6 clockwise from (22, 38.1) to (25.6, 34.5)
  arc A18 centre (-22, 34.5) radius 3.6 clockwise from (-25.6, 34.5) to (-22, 38.1)
  arc A19 centre (-15, -27.5) radius 10.6 clockwise from (-15, -38.1) to (-25.6, -27.5)
  arc A20 centre (15, -27.5) radius 10.6 clockwise from (25.6, -27.5) to (15, -38.1)
  arc A21 centre (-22, 34.5) radius 2.1 clockwise from (-24.1, 34.5) to (-22, 36.6)
  arc A22 centre (22, 34.5) radius 2.1 clockwise from (22, 36.6) to (24.1, 34.5)
  arc A23 centre (15, -27.5) radius 9.1 clockwise from (24.1, -27.5) to (15, -36.6)
  arc A24 centre (-15, -27.5) radius 9.1 clockwise from (-15, -36.6) to (-24.1, -27.5)
  dimension "d155" = 0.2
  dimension "d156" = -1.7
extrude "Extrude28" new body sketch "Sketch22" profile of C1 L21 L20 A17 L18 A18 L19 A20 A19 L22 A21 L23 L25 L24 A22 A24 A23 against normal blind 6
delete_face "DeleteFace14"
delete_face "DeleteFace15"
combine "Combine8"
copy_paste_bodies "CopyPasteBodies1"
position "Position11"
position "Position12"
position "Position13"
move_face "MoveFace7"
position "Position14"
sketch "Sketch23" plane through (0, 1.3, 0) normal (0, 1, 0) x axis (-1, 0, 0)
  line L1 (-22, 36.3) -> (22, 36.3)
  line L2 (-23.8, -27.5) -> (-23.8, 34.5)
  line L3 (15, -36.3) -> (-15, -36.3)
  line L4 (23.8, 34.5) -> (23.8, -27.5)
  line L5 (-16, 34.6) -> (16, 34.6)
  line L6 (-16, 33.5) -> (-16, 34.6)
  line L7 (16, 33.5) -> (-16, 33.5)
  line L8 (16, 34.6) -> (16, 33.5)
  line L9 (16, 34.05) -> (-16, 34.05)
  line L10 (-13, 34.05) -> (-16, 34.05)
  line L11 (-16, 32.55) -> (-13, 32.55)
  line L12 (-16, 35.55) -> (-16, 32.55)
  line L13 (-13, 35.55) -> (-16, 35.55)
  line L14 (-13, 32.55) -> (-13, 35.55)
  line L15 (-16, 35.55) -> (-13, 32.55)
  line L16 (-13, 35.55) -> (-16, 32.55)
  line L17 (13, 34.05) -> (16, 34.05)
  line L18 (16, 32.55) -> (13, 32.55)
  line L19 (16, 35.55) -> (16, 32.55)
  line L20 (13, 35.55) -> (16, 35.55)
  line L21 (13, 32.55) -> (13, 35.55)
  line L22 (16, 35.55) -> (13, 32.55)
  line L23 (13, 35.55) -> (16, 32.55)
  arc A1 centre (-22, 34.5) radius 1.8 clockwise from (-23.8, 34.5) to (-22, 36.3)
  arc A2 centre (-15, -27.5) radius 8.8 clockwise from (-15, -36.3) to (-23.8, -27.5)
  arc A3 centre (15, -27.5) radius 8.8 clockwise from (23.8, -27.5) to (15, -36.3)
  arc A4 centre (22, 34.5) radius 1.8 clockwise from (22, 36.3) to (23.8, 34.5)
  point P18 (-16, 34.05)
  point P19 (16, 34.05)
  point P25 (-14.5, 34.05)
  point P31 (14.5, 34.05)
  point P20 (-13, 34.05)
  point P23 (-16, 35.55)
  point P24 (-13, 35.55)
  point P22 (-16, 32.55)
  point P26 (13, 34.05)
  point P28 (16, 32.55)
  point P29 (16, 35.55)
  midpoint L6 P18
  midpoint L8 P19
  perpendicular L6 L10
  horizontal L11
  perpendicular L11 L12
  parallel L11 L13
  parallel L12 L14
  coincident L15 P25
  coincident L16 P25
  midpoint L10 P25
  perpendicular L8 L17
  horizontal L18
  perpendicular L18 L19
  parallel L18 L20
  parallel L19 L21
  coincident L22 P31
  coincident L23 P31
  midpoint L17 P31
  dimension "d159" distance P18 P20 = 3
  dimension "d160" distance P23 P24 = 3
  dimension "d161" distance P22 P23 = 3
  dimension "d162" distance P19 P26 = 3
  dimension "d163" distance P28 P29 = 3
extrude "Extrude29" add sketch "Sketch23" profile of L5 L6 L7 L8 L9 L10 L11 L12 L13 L14 L17 L18 L19 L20 L21 along normal blind 1.2
move_face "MoveFace8"
move_face "MoveFace9"
sketch "Sketch24" plane through (0, 1.3, 0) normal (0, 1, 0) x axis (-1, 0, 0)
  line L1 (13, 36.3) -> (13, 32.55)
  line L2 (-13, 36.3) -> (13, 36.3)
  line L3 (-13, 32.55) -> (-13, 36.3)
  line L4 (-16, 32.55) -> (-13, 32.55)
  line L5 (-16, 36.3) -> (-16, 32.55)
  line L6 (-22, 36.3) -> (-16, 36.3)
  line L7 (-23.8, -27.5) -> (-23.8, 34.5)
  line L8 (15, -36.3) -> (-15, -36.3)
  line L9 (23.8, 34.5) -> (23.8, -27.5)
  line L10 (16, 36.3) -> (22, 36.3)
  line L11 (16, 32.55) -> (16, 36.3)
  line L12 (13, 32.55) -> (16, 32.55)
  line L13 (-16, 37.5) -> (-13, 37.5)
  line L14 (-16, 32.55) -> (-16, 37.5)
  line L15 (-13, 32.55) -> (-16, 32.55)
  line L16 (-13, 37.5) -> (-13, 32.55)
  line L17 (13, 37.5) -> (16, 37.5)
  line L18 (13, 32.55) -> (13, 37.5)
  line L19 (16, 32.55) -> (13, 32.55)
  line L20 (16, 37.5) -> (16, 32.55)
  line L21 (18, 32.55) -> (16, 32.55)
  line L22 (18, 41.7199) -> (18, 32.55)
  line L23 (16, 41.7199) -> (18, 41.7199)
  line L24 (16, 32.55) -> (16, 41.7199)
  line L25 (-18, 32.55) -> (-16, 32.55)
  line L26 (-18, 42.6548) -> (-18, 32.55)
  line L27 (-16, 42.6548) -> (-18, 42.6548)
  line L28 (-16, 32.55) -> (-16, 42.6548)
  arc A1 centre (-22, 34.5) radius 1.8 clockwise from (-23.8, 34.5) to (-22, 36.3)
  arc A2 centre (-15, -27.5) radius 8.8 clockwise from (-15, -36.3) to (-23.8, -27.5)
  arc A3 centre (15, -27.5) radius 8.8 clockwise from (23.8, -27.5) to (15, -36.3)
  arc A4 centre (22, 34.5) radius 1.8 clockwise from (22, 36.3) to (23.8, 34.5)
  point P21 (16, 32.55)
  point P30 (16, 32.55)
  point P6 (-16, 32.55)
  point P34 (-16, 32.55)
  point P31 (18, 32.55)
  point P35 (-18, 32.55)
  horizontal L21
  vertical L22
  horizontal L23
  vertical L24
  coincident P21 P30
  horizontal L25
  vertical L26
  horizontal L27
  vertical L28
  coincident P6 P34
  dimension "d166" distance P30 P31 = 2
  dimension "d167" distance P34 P35 = 2
extrude "Extrude30" new body sketch "Sketch24" profile of L5 L6 L10 L11 L14 L20 L21 L22 L23 L24 L25 L26 L27 L28 along normal blind 21.2
combine "Combine9"
move_face "MoveFace10"
move_face "MoveFace11"
sketch "Sketch25" plane through (0, 2.5, 0) normal (0, 1, 0) x axis (-1, 0, 0)
  line L1 (13, 37.5) -> (16.2, 37.5)
  line L2 (13, 32.55) -> (13, 37.5)
  line L3 (16.2, 32.55) -> (13, 32.55)
  line L4 (16.2, 37.5) -> (16.2, 32.55)
  line L5 (-16.2, 37.5) -> (-13, 37.5)
  line L6 (-16.2, 32.55) -> (-16.2, 37.5)
  line L7 (-13, 32.55) -> (-16.2, 32.55)
  line L8 (-13, 37.5) -> (-13, 32.55)
  line L9 (16.2, 37.5) -> (-16.2, 37.5)
  line L10 (-14.5, 40.995) -> (-16.2, 40.995)
  line L11 (-14.5, 35.025) -> (-14.5, 40.995)
  line L12 (-16.2, 35.025) -> (-14.5, 35.025)
  line L13 (-16.2, 40.995) -> (-16.2, 35.025)
  line L14 (14.2, 42.8077) -> (16.2, 42.8077)
  line L15 (14.2, 29.7032) -> (14.2, 42.8077)
  line L16 (16.2, 29.7032) -> (14.2, 29.7032)
  line L17 (16.2, 42.8077) -> (16.2, 29.7032)
  line L18 (20.9381, 35.025) -> (-14.5, 35.025)
  point P7 (-16.2, 37.5)
  point P10 (-16.2, 37.5)
  point P2 (16.2, 37.5)
  point P11 (16.2, 37.5)
  point P12 (-16.2, 40.995)
  point P13 (-14.5, 40.995)
  point P16 (16.2, 42.8077)
  point P17 (14.2, 42.8077)
  coincident P7 P10
  coincident P2 P11
  horizontal L10
  vertical L11
  horizontal L12
  vertical L13
  horizontal L14
  vertical L15
  horizontal L16
  vertical L17
  perpendicular L17 L18
  dimension "d170" distance P12 P13 = 1.7
  dimension "d171" distance P16 P17 = 2
extrude "Extrude31" add sketch "Sketch25" profile of L1 L4 L5 L6 L9 L11 L12 L13 L15 L17 L18 along normal blind 20
delete_face "DeleteFace16"
delete_face "DeleteFace17"
delete_face "DeleteFace18"
delete_face "DeleteFace19"
sketch "Sketch26" plane through (0, 1.3, 0) normal (0, 1, 0) x axis (-1, 0, 0)
  line L1 (-18, 36.3) -> (-18, 32.55)
  line L2 (-22, 36.3) -> (-18, 36.3)
  line L3 (-23.8, -27.5) -> (-23.8, 34.5)
  line L4 (23.8, 34.5) -> (23.8, -27.5)
  line L5 (18, 36.3) -> (22, 36.3)
  line L6 (18, 32.55) -> (18, 36.3)
  line L7 (13, 32.55) -> (18, 32.55)
  line L8 (13, 36.3) -> (13, 32.55)
  line L9 (-13, 36.3) -> (13, 36.3)
  line L10 (-13, 32.55) -> (-13, 36.3)
  line L11 (-18, 32.55) -> (-13, 32.55)
  line L12 (11.75, -38.15) -> (-11.75, -38.15)
  line L13 (-13.75, -37.15) -> (-13.75, 21.15)
  line L14 (11.75, -39.15) -> (-11.75, -39.15)
  line L15 (13.75, 21.15) -> (13.75, -37.15)
  line L16 (-11.75, 23.15) -> (11.75, 23.15)
  arc A1 centre (-22, 34.5) radius 1.8 clockwise from (-23.8, 34.5) to (-22, 36.3)
  arc A2 centre (-15, -27.5) radius 8.8 clockwise from (-15, -36.3) to (-23.8, -27.5)
  arc A3 centre (15, -27.5) radius 8.8 clockwise from (23.8, -27.5) to (15, -36.3)
  arc A4 centre (22, 34.5) radius 1.8 clockwise from (22, 36.3) to (23.8, 34.5)
  arc A5 centre (11.75, -37.15) radius 1 clockwise from (12.75, -37.15) to (11.75, -38.15)
  arc A6 centre (11.75, 21.15) radius 1 clockwise from (11.75, 22.15) to (12.75, 21.15)
  arc A7 centre (-11.75, 21.15) radius 1 clockwise from (-12.75, 21.15) to (-11.75, 22.15)
  arc A8 centre (-11.75, -37.15) radius 1 clockwise from (-11.75, -38.15) to (-12.75, -37.15)
  arc A9 centre (-11.75, -37.15) radius 2 clockwise from (-11.75, -39.15) to (-13.75, -37.15)
  arc A10 centre (11.75, -37.15) radius 2 clockwise from (13.75, -37.15) to (11.75, -39.15)
  arc A11 centre (11.75, 21.15) radius 2 clockwise from (11.75, 23.15) to (13.75, 21.15)
  arc A12 centre (-11.75, 21.15) radius 2 clockwise from (-13.75, 21.15) to (-11.75, 23.15)
extrude "Extrude32" new body sketch "Sketch26" profile of L16 A10 A9 L13 A12 A11 L14 L15 along normal blind 4
combine "Combine10"
sketch "Sketch27" plane through (0, 1.3, 0) normal (0, 1, 0) x axis (-1, 0, 0)
  line L1 (13.75, -36.3) -> (13.75, 21.15)
  line L2 (15, -36.3) -> (13.75, -36.3)
  line L3 (23.8, 34.5) -> (23.8, -27.5)
  line L4 (18, 36.3) -> (22, 36.3)
  line L5 (18, 32.55) -> (18, 36.3)
  line L6 (13, 32.55) -> (18, 32.55)
  line L7 (13, 36.3) -> (13, 32.55)
  line L8 (-13, 36.3) -> (13, 36.3)
  line L9 (-13, 32.55) -> (-13, 36.3)
  line L10 (-18, 32.55) -> (-13, 32.55)
  line L11 (-18, 36.3) -> (-18, 32.55)
  line L12 (-22, 36.3) -> (-18, 36.3)
  line L13 (-23.8, -27.5) -> (-23.8, 34.5)
  line L14 (-13.75, -36.3) -> (-15, -36.3)
  line L15 (-13.75, 21.15) -> (-13.75, -36.3)
  line L16 (11.75, 23.15) -> (-11.75, 23.15)
  line L17 (0, -36.3) -> (0, 23.15)
  line L18 (-35.8461, -5.575) -> (35.8461, -5.575)
  line L19 (-35.8461, -7.575) -> (-35.8461, -5.575)
  line L20 (35.8461, -7.575) -> (-35.8461, -7.575)
  line L21 (35.8461, -5.575) -> (35.8461, -7.575)
  line L22 (-35.8461, -7.575) -> (35.8461, -5.575)
  line L23 (35.8461, -7.575) -> (-35.8461, -5.575)
  arc A1 centre (15, -27.5) radius 8.8 clockwise from (23.8, -27.5) to (15, -36.3)
  arc A2 centre (22, 34.5) radius 1.8 clockwise from (22, 36.3) to (23.8, 34.5)
  arc A3 centre (-22, 34.5) radius 1.8 clockwise from (-23.8, 34.5) to (-22, 36.3)
  arc A4 centre (-15, -27.5) radius 8.8 clockwise from (-15, -36.3) to (-23.8, -27.5)
  arc A5 centre (-11.75, 21.15) radius 2 clockwise from (-13.75, 21.15) to (-11.75, 23.15)
  arc A6 centre (11.75, 21.15) radius 2 clockwise from (11.75, 23.15) to (13.75, 21.15)
  point P30 (0, 23.15)
  point P36 (0, -6.575)
  point P33 (-35.8461, -5.575)
  point P34 (-35.8461, -7.575)
  midpoint L16 P30
  perpendicular L14 L17
  horizontal L18
  perpendicular L18 L19
  parallel L18 L20
  parallel L19 L21
  coincident L22 P36
  coincident L23 P36
  midpoint L17 P36
  dimension "d177" distance P33 P34 = 2
extrude "Extrude33" new body sketch "Sketch27" profile of L1 L3 L13 L15 L18 L20 along normal blind 7
sketch "Sketch28" plane through (0, 0, -39.5) normal (0, 0, -1) x axis (1, 0, 0)
  line L1 (-15, -1.8) -> (15, -1.8)
  line L2 (-15, -25) -> (-15, -1.8)
  line L3 (15, -25) -> (-15, -25)
  line L4 (15, -1.8) -> (15, -25)
  line L5 (3.5, -6.85) -> (-3.5, -6.85)
  line L6 (4.5, -9.05) -> (4.5, -7.85)
  line L7 (-3.5, -10.05) -> (3.5, -10.05)
  line L8 (-4.5, -7.85) -> (-4.5, -9.05)
  line L9 (-3.5, -11.05) -> (3.5, -11.05)
  line L10 (5.5, -9.05) -> (5.5, -7.85)
  line L11 (3.5, -5.85) -> (-3.5, -5.85)
  line L12 (-5.5, -7.85) -> (-5.5, -9.05)
  arc A1 centre (-3.5, -7.85) radius 1 clockwise from (-4.5, -7.85) to (-3.5, -6.85)
  arc A2 centre (3.5, -7.85) radius 1 clockwise from (3.5, -6.85) to (4.5, -7.85)
  arc A3 centre (3.5, -9.05) radius 1 clockwise from (4.5, -9.05) to (3.5, -10.05)
  arc A4 centre (-3.5, -9.05) radius 1 clockwise from (-3.5, -10.05) to (-4.5, -9.05)
  arc A5 centre (-3.5, -9.05) radius 2 clockwise from (-3.5, -11.05) to (-5.5, -9.05)
  arc A6 centre (3.5, -9.05) radius 2 clockwise from (5.5, -9.05) to (3.5, -11.05)
  arc A7 centre (3.5, -7.85) radius 2 clockwise from (3.5, -5.85) to (5.5, -7.85)
  arc A8 centre (-3.5, -7.85) radius 2 clockwise from (-5.5, -7.85) to (-3.5, -5.85)
  dimension "d180" = -1
extrude "Extrude34" cut sketch "Sketch28" profile of A1 L5 A2 L6 A3 L7 A4 L8 L9 L10 L12 L11 A6 A5 A7 A8 against normal blind 1.2
move_face "MoveFace12"
move_face "MoveFace13"
move_face "MoveFace14"
move_face "MoveFace15"
rectangular_pattern "R-Pattern4" uSpaceDistance -22 vSpaceDistance 0
mirror "Mirror2" mirrorStitchTolerance 0.1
